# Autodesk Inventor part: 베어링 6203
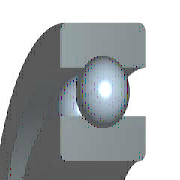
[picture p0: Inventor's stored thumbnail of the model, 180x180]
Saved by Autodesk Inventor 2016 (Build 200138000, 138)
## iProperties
IsCustomPart: 0
Created: 2014-10
Part Number: 베어링 6203
Material: 강철, 연강
Description: 깊은 그루브 볼 베어링
Document SubType Name: Modeling
Standard: KS B 2023
Designer: KYOUNG IL JANG
Standards Organization: KS
Language: ko-KR
Size Designation: 6203 - 17 x 40 x 12
Categories: <MemberInstance><Categories><Category DisplayName="샤프트 부품" InternalName="7f7aeb1f-a693-4053-b835-cee3144e0d98" Mnemonic="SHFT"><Category DisplayName="베어링" Inter
Density: 2.71 g/cm^3
Mass: 22.4044 g
Surface Area: 64.3582 cm^2
Volume: 8.26729 cm^3
Appearance: 노란색
Author: SeoGD™ [www.esajin.kr]
Revision Number: 1
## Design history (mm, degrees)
sketch "스케치" dims "d0" = 5.98 (= -0.26 x WD + 0.26 x BD)
  geometry: L1 (3.01, 14.25)-(8.99, 14.25); L2 (6, 14.25)-(6, 11.26); L3 (6, 14.25)-(6, 17.24); L4 (3.778, 12.249)-(0, 12.249); L5 (0, 8.5)-(12, 8.5); L6 (3.778, 16.251)-(0, 16.251); L7 (0, 20)-(12, 20); L8 (12, 8.5)-(12, 12.249); L9 (8.222, 12.249)-(12, 12.249); L10 (8.222, 16.251)-(12, 16.251); L11 (12, 20)-(12, 16.251); L12 (-1.4, 0)-(8.4, 0) reference; L13 (0, -0.3)-(0, 5.3) reference
  constraints: 22 end point, 4 point on line, 2 collinear, 2 perpendicular, 2 symmetric about line, 1 midpoint, 1 parallel, 14 other
  dimensions: "d9" = 17 diameter of L5 L12 (= WD); "d11" = 40 diameter of L7 L12 (= BD); "d12" = 12 distance between parallel lines of L8 L13 (= KB); "d13" = 24.498 diameter of L9 L12 (= 0.326 x BD + 0.674 x WD)
revolve "본체" stored, may be unused: angle "d6" = 90 deg
revolve "볼" stored, may be unused: angle "d7" = 90 deg
pattern_circular "IDS_ARRAYBALL[SIMPL:T]" dims angle "d3" = 360 deg
body "Solid1"
fillet "모깎기1" dims "d1" = 0.6 (= KRS)
other parameters: "WD" = 17 [user parameter; used in 5 equation terms], "BD" = 40 [user parameter; used in 5 equation terms], "KB" = 12 [user parameter; used in 1 equation term], "KRS" = 0.6 [user parameter; used in 1 equation term], "d4" = 0, "d5" = 0, "d8" = 0, "d14" = 0, "d15" = 0, "BBA" = 0 [user parameter], "BC0" = 4750000 [user parameter], "BC" = 9560000 [user parameter], "WR" = 8.5 (= 0.5 x WD) [user parameter]
